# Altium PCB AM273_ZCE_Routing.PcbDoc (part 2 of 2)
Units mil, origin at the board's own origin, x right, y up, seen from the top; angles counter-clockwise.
Board outline 825 x 1150 mil, 4 copper layers (Top Layer, GND, Power, Bottom Layer), stack 60.63 mil thick; 37 components, 157 nets, 353 pads, 168 vias.
Unrouted connection lines stored in the file: 5.
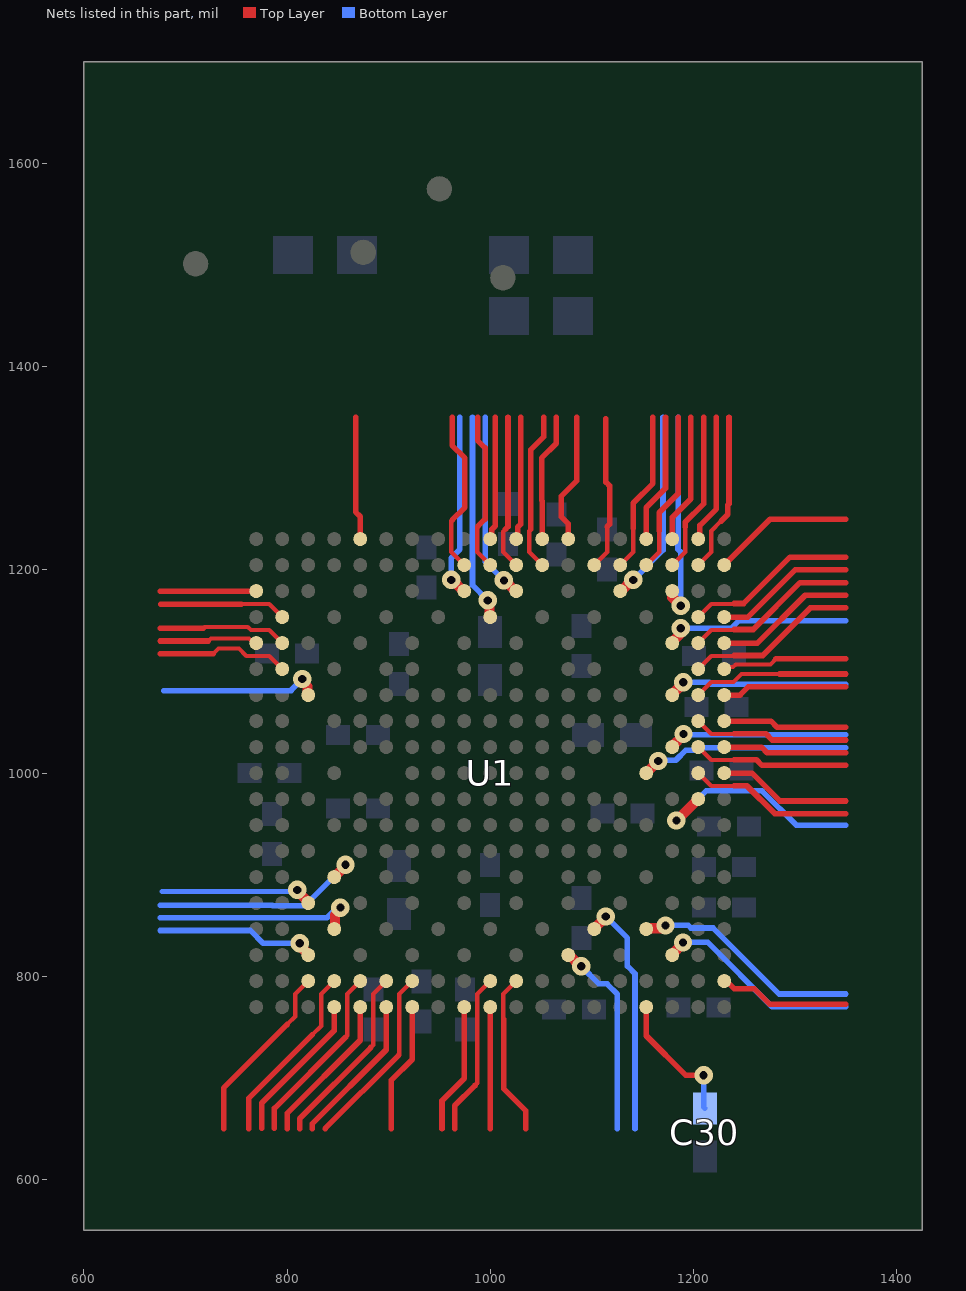
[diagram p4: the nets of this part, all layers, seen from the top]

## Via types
v1: diameter 18, hole 8, Top Layer to Bottom Layer, tented both sides, 168 vias

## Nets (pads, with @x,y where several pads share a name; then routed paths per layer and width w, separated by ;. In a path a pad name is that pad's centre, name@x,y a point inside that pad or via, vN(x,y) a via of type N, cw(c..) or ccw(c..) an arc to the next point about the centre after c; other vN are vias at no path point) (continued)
MSS_QSPI_CLK: U1.E1 | length 149.5
  Top Layer w5.5: 800,650 800,665 872.05,737.05 U1.E1@872.05,769.68
MSS_QSPI_CS: U1.F2 | length 180.5
  Top Layer w4: 882.5,730 884.84,732.34 884.84,782.48 U1.F2@897.64,795.28
  Top Layer w5.5: 812.5,650 812.5,660 882.5,730
MSS_QSPI_D0: U1.C2 | length 179.8
  Top Layer w4: 800,752.5 808.07,760.57 808.07,782.48 U1.C2@820.87,795.28
  Top Layer w5.5: 737.5,650 737.5,690 800,752.5
MSS_QSPI_D1: U1.D2 | length 180.1
  Top Layer w4: 825,742.5 833.66,751.16 833.66,782.48 U1.D2@846.46,795.28
  Top Layer w5.5: 762.5,650 762.5,680 825,742.5
MSS_QSPI_D2: U1.D1 | length 149
  Top Layer w5.5: 775,650.28 775,675 846.46,746.46 U1.D1@846.46,769.68
MSS_QSPI_D3: U1.E2 | length 180
  Top Layer w4: 857.5,740 859.25,741.75 859.25,782.48 U1.E2@872.05,795.28
  Top Layer w5.5: 787.5,650.28 787.5,670 857.5,740
MSS_RGMII_RCLK: U1.M19 | length 125.9
  Top Layer w5.5: U1.M19@1051.18,1230.32 1051.18,1267.69 1050.58,1268.3 1050.58,1310 1065,1324.42 1065,1350
MSS_RGMII_RCTL: U1.J17 | length 180.7
  Top Layer w10: v1(961.61,1190.14) 962.51,1190.14 973.51,1179.13 U1.J17@974.41,1179.13
  Bottom Layer w5.5: v1(961.61,1190.14) 961.61,1211.61 970,1220 970,1350
MSS_RGMII_RD0: U1.P18 | length 152
  Top Layer w4: U1.P18@1102.36,1204.72 1115.16,1217.52 1115.16,1242.34 1115,1242.5
  Top Layer w5.5: 1113.86,1348.86 1113.86,1286.36 1117.5,1282.73 1117.5,1245 1115,1242.5
MSS_RGMII_RD1: U1.N19 | length 128.7
  Top Layer w5.5: U1.N19@1076.77,1230.32 1076.71,1230.38 1076.71,1245.45 1070,1252.16 1070,1272.5 1085,1287.5 1085,1350
MSS_RGMII_RD2: U1.M18 | length 156.4
  Top Layer w4: 1040,1240 1038.39,1238.39 1038.39,1217.52 U1.M18@1051.18,1204.72
  Top Layer w5.5: 1040,1240 1040,1318.33 1052.5,1330.83 1052.5,1350
MSS_RGMII_RD3: U1.L19 | length 121.5
  Top Layer w5.5: U1.L19@1025.59,1230.32 1027.17,1231.9 1027.17,1242.17 1030,1245 1030,1350
MSS_RGMII_TCLK: U1.K19 | length 121.8
  Top Layer w5.5: U1.K19@1000,1230.32 1001.58,1231.9 1001.58,1240 1005,1243.42 1005,1350
MSS_RGMII_TCTL: U1.J18 | length 161.3
  Top Layer w4: 962.51,1248.98 961.61,1248.08 961.61,1217.52 U1.J18@974.41,1204.72
  Top Layer w5.5: 962.51,1248.98 975,1261.46 975,1310 962.5,1322.5 962.5,1350
MSS_RGMII_TD0: U1.L18 | length 152.5
  Top Layer w4: 1015,1240 1012.8,1237.8 1012.8,1217.52 U1.L18@1025.59,1204.72
  Top Layer w5.5: 1015,1240 1017.5,1242.5 1017.5,1350
MSS_RGMII_TD1: U1.L17 | length 184.5
  Top Layer w10: v1(1013.38,1189.64) 1014.23,1189.64 1024.74,1179.13 U1.L17@1025.59,1179.13
  Bottom Layer w5.5: 995,1350 995,1208.02 v1(1013.38,1189.64)
MSS_RGMII_TD2: U1.K16 | length 203.7
  Top Layer w10: v1(997.5,1170) 997.5,1167.84 999.28,1166.06 999.28,1154.27 U1.K16@1000,1153.54
  Bottom Layer w5.5: 982.5,1350 982.5,1185 v1(997.5,1170)
MSS_RGMII_TD3: U1.K18 | length 156.9
  Top Layer w4: 987.5,1242.5 987.21,1242.21 987.21,1217.52 U1.K18@1000,1204.72
  Top Layer w5.5: 987.5,1242.5 995,1250 995,1320 987.5,1327.5 987.5,1350
MSS_RS232_RX: U1.G2 | length 180.8
  Top Layer w4: 910,722.5 910.43,722.93 910.43,782.48 U1.G2@923.23,795.28
  Top Layer w5.5: 837.5,650 910,722.5
MSS_RS232_TX: U1.G1 | length 128.3
  Top Layer w5.5: 902.5,650 902.5,697.5 923.23,718.23 U1.G1@923.23,769.68
MSS_UARTA_RX: U1.U3 | length 203.2
  Top Layer w10: U1.U3@1179.13,820.87 1179.13,821.73 1189.8,832.4 v1(1189.8,833.26)
  Bottom Layer w5.5: v1(1189.8,833.26) 1214.24,833.26 1277.5,770 1350,770
MSS_UARTA_TX: U1.W2 | length 129.1
  Top Layer w5.5: U1.W2@1230.32,795.28 1232.56,795.28 1240.33,787.5 1260,787.5 1275,772.5 1350,772.5
MSS_UARTB_TX: U1.V9 | length 223.2
  Top Layer w10: v1(1183.19,953.19) 1183.35,953.19 1204.57,974.41 U1.V9@1204.72,974.41
  Bottom Layer w5.5: v1(1183.19,953.19) 1212.5,982.5 1267.5,982.5 1301.18,948.82 1350,948.82
OSC_CLK_OUT_AUDIO: U1.T4 | length 228.2
  Top Layer w10: U1.T4@1153.54,846.46 1154.27,847.18 1167.52,847.18 1170.34,850 v1(1172.5,850)
  Bottom Layer w5.5: v1@1167.5,852.5 v1@1169.17,854.17 ; v1(1172.5,850) 1195,850 1197.5,847.5 1219.4,847.5 1284.4,782.5 1350,782.5
PMIC_CLKOUT: U1.F1 | length 149.8
  Top Layer w5.5: 825,650 825,655 897.64,727.64 U1.F1@897.64,769.68
R\E\S\E\T\: U1.L2 | length 159.8
  Top Layer w4: 1013.09,757.5 1012.8,757.79 1012.8,782.48 U1.L2@1025.59,795.28
  Top Layer w5.5: 1013.09,757.5 1013.09,689.41 1035,667.5 1035,650
R\E\S\E\T\_\F\E\1\: U1.A15 | length 97.6
  Top Layer w4: 722.5,1130 725,1132.5 762.49,1132.5 767.04,1127.95 U1.A15@769.68,1127.95
  Top Layer w5.5: 675,1130 722.5,1130
R\E\S\E\T\_\F\E\2\: U1.B15 | length 127.4
  Top Layer w4: 717.43,1142.5 718.75,1143.82 761.32,1143.82 764.39,1140.75 765,1140.75 782.48,1140.75 U1.B15@795.28,1127.95
  Top Layer w5.5: 675,1142.5 717.43,1142.5
RCSS_GPIO_49: U1.E19 | length 121.6
  Top Layer w5.5: 867.5,1350 867.5,1257.05 872.05,1252.5 U1.E19@872.05,1230.32
RCSS_MIBSPIA_CLK: U1.T18 | length 158.3
  Top Layer w4: U1.T18@1153.54,1204.72 1166.34,1217.52 1166.34,1238.66
  Top Layer w5.5: 1166.34,1238.66 1166.34,1256.34 1185,1275 1185,1350
RCSS_MIBSPIA_CS0: U1.T19 | length 127.5
  Top Layer w5.5: U1.T19@1153.54,1230.32 1153.54,1261.31 1172.5,1280.27 1172.5,1350
RCSS_MIBSPIA_HOSTIRQ: U1.U18 | length 158.1
  Top Layer w4: U1.U18@1179.13,1204.72 1191.93,1217.52 1191.93,1242.36
  Top Layer w5.5: 1191.93,1242.36 1191.93,1246.93 1210,1265 1210,1350
RCSS_MIBSPIA_MISO: U1.R17 | length 189.3
  Top Layer w10: U1.R17@1127.95,1179.13 1128.85,1179.13 1139.85,1190.14 v1(1140.75,1190.14)
  Bottom Layer w5.5: v1(1140.75,1190.14) 1170,1219.39 1170,1350
RCSS_MIBSPIA_MOSI: U1.R18 | length 158.5
  Top Layer w4: U1.R18@1127.95,1204.72 1140.75,1217.52 1140.75,1240.75
  Top Layer w5.5: 1140.75,1240.75 1140.75,1265.75 1160,1285 1160,1350
RCSS_MIBSPIB_CLK: U1.V19 | length 127
  Top Layer w5.5: U1.V19@1204.72,1230.32 1206.31,1231.9 1206.31,1243.81 1222.5,1260 1222.5,1350
RCSS_MIBSPIB_CS0: U1.U17 | length 204.5
  Top Layer w10: U1.U17@1179.13,1179.13 1179.13,1173.01 v1(1187.5,1164.64)
  Bottom Layer w5.5: 1185,1350 1185,1225 1184.78,1224.78 1184.78,1220.22 1187.5,1217.5 v1(1187.5,1164.64)
RCSS_MIBSPIB_HOSTIRQ: U1.W18 | length 138.4
  Top Layer w5.5: U1.W18@1230.32,1204.72 1275.59,1250 1350,1250
RCSS_MIBSPIB_MISO: U1.V18 | length 157.8
  Top Layer w4: U1.V18@1204.72,1204.72 1217.52,1217.52 1217.52,1238.27 1227.33,1248.08
  Top Layer w5.5: 1227.33,1248.08 1233.78,1254.53 1233.78,1263.78 1235,1265 1235,1350
RCSS_MIBSPIB_MOSI: U1.U19 | length 127.3
  Top Layer w5.5: U1.U19@1179.13,1230.32 1179.13,1251.63 1197.5,1270 1197.5,1350
RCSS_UARTA_RX: U1.B16 | length 124.8
  Top Layer w4: 755,1166.34 782.48,1166.34 U1.B16@795.28,1153.54
  Top Layer w5.5: 675.75,1166.34 755,1166.34
RCSS_UARTA_TX: U1.A17 | length 94.7
  Top Layer w5.5: 675,1179.13 U1.A17@769.68,1179.13
TCK: U1.C3 | length 157.8
  Top Layer w10: v1(812.5,832.5) 812.5,830.34 815.56,827.27 815.56,827.19 820.87,821.89 U1.C3@820.87,820.87
  Bottom Layer w5.5: 675,845 763.9,845 776.4,832.5 v1(812.5,832.5)
TDI: U1.C5 | length 151
  Top Layer w10: v1(810,885) 810,883.94 820.87,873.07 U1.C5@820.87,872.05
  Bottom Layer w5: 677.04,883.55 808.55,883.55 v1(810,885)
TDO: U1.D6 | length 226.7
  Top Layer w10: U1.D6@846.46,897.64 857.5,908.68 v1(857.5,909.68)
  Bottom Layer w5.5: 675,870 785.36,870 786.11,869.25 817.07,869.25 v1(857.5,909.68) 857.18,909.68 850,902.5
TEMP_1_SENSOR: U1.P4 | length 237.8
  Top Layer w10: U1.P4@1102.36,846.46 1102.36,846.95 1113.74,858.33 v1(1113.74,858.83)
  Bottom Layer w5.5: v1(1113.74,858.83) 1135,837.58 1135,810 1142.5,802.5 1142.5,650
TEMP_2_SENSOR: U1.N3 | length 196.6
  Top Layer w10: U1.N3@1076.77,820.87 1077.67,820.87 1088.67,809.86 v1(1089.57,809.86)
  Bottom Layer w5.5: v1(1089.57,809.86) 1106.93,792.5 1115,792.5 1125,782.5 1125,650
TMS: U1.D4 | length 205.2
  Top Layer w10: U1.D4@846.46,846.46 847.18,847.18 847.18,860.01 852.5,865.34 v1(852.5,867.5)
  Bottom Layer w5.5: 675,857.5 839.12,857.5 849.12,867.5 v1(852.5,867.5)
TRACE_CLK: U1.W12 | length 122.2
  Top Layer w5.5: U1.W12@1230.32,1051.18 1276.32,1051.18 1282.5,1045 1350,1045
TRACE_CTL: U1.V12 | length 153.3
  Top Layer w4: U1.V12@1204.72,1051.18 1217.52,1038.39 1239.71,1038.39 1240,1038.68
  Top Layer w5.5: 1240,1038.68 1271.32,1038.68 1277.5,1032.5 1350,1032.5
TRACE_D0: U1.V16 | length 169.4
  Top Layer w4: U1.V16@1204.72,1153.54 1217.52,1166.34 1239.43,1166.34 1240,1166.91
  Top Layer w5.5: 1240,1166.91 1249.41,1166.91 1295,1212.5 1349.72,1212.5
TRACE_D1: U1.U15 | length 183.6
  Top Layer w10: U1.U15@1179.13,1127.95 1179.13,1128.98 1185.97,1135.81 1185.97,1140.97 v1(1187.5,1142.5)
  Bottom Layer w5.5: v1(1187.5,1142.5) 1237.5,1142.5 1245,1150 1350,1150
TRACE_D2: U1.W16 | length 138.9
  Top Layer w5.5: U1.W16@1230.32,1153.54 1253.54,1153.54 1300,1200 1350,1200
TRACE_D3: U1.V15 | length 169.9
  Top Layer w4: U1.V15@1204.72,1127.95 1217.52,1140.75 1239.43,1140.75 1240,1141.32
  Top Layer w5.5: 1240,1141.32 1258.82,1141.32 1305,1187.5 1350,1187.5
TRACE_D4: U1.W15 | length 139.2
  Top Layer w5.5: U1.W15@1230.32,1127.95 1262.95,1127.95 1310,1175 1350,1175
TRACE_D5: U1.V14 | length 170.2
  Top Layer w4: U1.V14@1204.72,1102.36 1217.52,1115.16 1239.43,1115.16 1240,1115.73
  Top Layer w5.5: 1240,1115.73 1268.23,1115.73 1315,1162.5 1350,1162.5
TRACE_D6: U1.U13 | length 177.8
  Top Layer w10: U1.U13@1179.13,1076.77 1179.13,1077.65 1189.92,1088.43 v1(1189.92,1089.31)
  Bottom Layer w5.5: v1(1189.92,1089.31) 1215.69,1089.31 1217.5,1087.5 1350,1087.5
TRACE_D7: U1.W14 | length 123.9
  Top Layer w4: U1.W14@1230.32,1102.36 1232.19,1104.23 1238.91,1104.23 1241.65,1106.98 1275.73,1106.98 1281.25,1112.5
  Top Layer w5.5: 1281.25,1112.5 1350,1112.5
TRACE_D8: U1.V13 | length 153.9
  Top Layer w4: U1.V13@1204.72,1076.77 1217.52,1089.57 1239.57,1089.57 1247.5,1097.5 1285,1097.5
  Top Layer w5.5: 1285,1097.5 1350,1097.5
TRACE_D9: U1.W13 | length 123.1
  Top Layer w5.5: U1.W13@1230.32,1076.77 1245.83,1076.77 1254.06,1085 1350,1085
TRACE_D10: U1.U11 | length 177.6
  Top Layer w10: U1.U11@1179.13,1025.59 1179.13,1026.49 1190.14,1037.49 v1(1190.14,1038.39)
  Bottom Layer w5.5: v1(1190.14,1038.39) 1191.02,1037.5 1350,1037.5
TRACE_D11: U1.V11 | length 153
  Top Layer w4: U1.V11@1204.72,1025.59 1217.52,1012.8 1239.71,1012.8 1240,1013.09
  Top Layer w5.5: 1240,1013.09 1261.91,1013.09 1267.5,1007.5 1350,1007.5
TRACE_D12: U1.W11 | length 122
  Top Layer w5.5: U1.W11@1230.32,1025.59 1266.91,1025.59 1272.5,1020 1350,1020
TRACE_D13: U1.V10 | length 162.1
  Top Layer w4: U1.V10@1204.72,1000 1217.52,987.21 1239.71,987.21 1240,987.5
  Top Layer w5.5: 1240,987.5 1252.5,987.5 1280,960 1350,960
TRACE_D14: U1.W10 | length 131.1
  Top Layer w5.5: U1.W10@1230.32,1000 1257.5,1000 1285,972.5 1350,972.5
TRACE_D15: U1.T10 | length 206.9
  Top Layer w10: U1.T10@1153.54,1000 1153.54,1000.09 1165.32,1011.87 v1(1165.32,1011.96)
  Bottom Layer w5.5: v1(1165.32,1011.96) 1165.94,1012.57 1182.57,1012.57 1192.5,1022.5 1202.5,1022.5 1205,1025 1350,1025
VBGAP: C30.1 U1.T1 | length 133.9
  Top Layer w5.5: U1.T1@1153.54,769.68 1153.54,741.46 1192.5,702.5 v1(1210,702.5)
  Bottom Layer w5.5: v1(1210,702.5) 1210,671.28 C30.1@1211.28,670
W\A\R\M\R\E\S\E\T\_\I\N\_\F\E\1\: U1.B14 | length 130.7
  Top Layer w4: 727.5,1117.5 732.5,1122.5 752.5,1122.5 759.84,1115.16 782.48,1115.16 U1.B14@795.28,1102.36
  Top Layer w5.5: 675,1117.5 727.5,1117.5
W\A\R\M\R\E\S\E\T\_\I\N\_\F\E\2\: U1.C13 | length 159.8
  Top Layer w10: v1(815,1092.5) 815,1090.34 820.14,1085.19 820.14,1077.49 U1.C13@820.87,1076.77
  Bottom Layer w5.5: 678.48,1080.98 804.02,1080.98 804.02,1081.52 v1(815,1092.5)
WARM_RESET: U1.K1 | length 119.7
  Top Layer w5.5: 1000,650 U1.K1@1000,769.68
XREF_CLK0: U1.J1 | length 128.8
  Top Layer w5.5: 952.5,650 952.5,677.5 974.41,699.41 U1.J1@974.41,769.68
XREF_CLK1: U1.K2 | length 159.8
  Top Layer w4: 985,692.5 987.21,694.71 987.21,782.48 U1.K2@1000,795.28
  Top Layer w5.5: 965,650 965,672.5 985,692.5

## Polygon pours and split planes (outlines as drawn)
1V8_AM273 on Top Layer "TOP_LAYER_1V8_AM273_P039" (solid, remove dead copper, pour order 39): 1170,932.5 1195,932.5 1195,875 1185,865 1170,865 1157.5,877.5 1157.5,920
1V2_VDD on Top Layer "TOP_LAYER_1V2_VDD_P002" (solid, remove dead copper, pour order 2): 922.5,900 922.5,865 970,817.5 992.5,817.5 992.5,852.5 1072.5,852.5 1085,865 1085,895 1080,900
GND on Top Layer "TOP_LAYER_GND_P036" (solid, remove dead copper, pour order 36): 755,1462.5 755,1530 825,1600 1092.5,1600 1152.5,1540 1152.5,1437.5 1112.5,1437.5 1000,1550 837.5,1550 825,1537.5 825,1462.5
1V8_AM273 on Top Layer "TOP_LAYER_1V8_AM273_P035" (solid, remove dead copper, pour order 35): 675,1540 675,1505 697.5,1482.5 722.5,1482.5 745,1505 745,1540
3V3_AM273 on Top Layer "TOP_LAYER_3V3_AM273_P033" (solid, remove dead copper, pour order 33): 925,1462.5 925,1540 850,1540 850,1462.5
1V2_VDD on Top Layer "TOP_LAYER_1V2_VDD_P032" (solid, remove dead copper, pour order 32): 942.5,1537.5 942.5,1437.5 992.5,1437.5 1030,1475 1030,1500 992.5,1537.5
GND on Top Layer "TOP_LAYER_GND_P024" (solid, remove dead copper, pour order 24): 675,1350 1350,1350 1350,650 675,650
1V2_VDD on Top Layer "TOP_LAYER_1V2_VDD_P012" (solid, remove dead copper, pour order 12): 1072.5,1212.5 1055,1195 993.61,1130 1092.5,1130 1092.5,1180 1097.5,1185 1097.5,1197.5 1082.5,1212.5
1V8_AM273 on Top Layer "TOP_LAYER_1V8_AM273_P010" (solid, remove dead copper, pour order 10): 805,940 817.5,940 830,952.5 830,1037.5 817.5,1050 805,1050
GND on Top Layer "TOP_LAYER_GND_P004" (solid, remove dead copper, pour order 4): 897.5,1117.5 820,1040 820,917.5 865,917.5 865,870 890,870 937.5,917.5 1072.5,917.5 1100,890 1160,890 1170,900 1170,1155 1157.5,1167.5 1117.5,1167.5 1067.5,1117.5
1V2_VDD on Top Layer "TOP_LAYER_1V2_VDD_P003" (solid, remove dead copper, pour order 3): 1100,1027.5 1135,1027.5 1145,1017.5 1145,982.5 1135,972.5 1100,972.5
1V2_VDD on Top Layer "TOP_LAYER_1V2_VDD_P001" (solid, remove dead copper, pour order 1): 900,1027.5 900,972.5 867.5,972.5 855,985 855,1017.5 865,1027.5
1V2_VDD on Top Layer "TOP_LAYER_1V2_VDD_P000" (solid, remove dead copper, pour order 0): 915,1135 925,1145 1090,1145 1090,1115 1075,1100 925,1100 915,1110
1V2_VDD on Bottom Layer "BOTTOM_LAYER_1V2_VDD_P011" (solid, remove dead copper, pour order 11): 1007.5,1237.5 1072.5,1237.5 1100,1210 1100,1185 1095,1180 1040,1180 1007.5,1212.5
GND on Bottom Layer "BOTTOM_LAYER_GND_P040" (solid, remove dead copper, pour order 40): 827.5,1540 750,1540 750,1450 827.5,1450
GND on Bottom Layer "BOTTOM_LAYER_GND_P029" (solid, remove dead copper, pour order 29): 1060,1540 1150,1540 1150,1430 1060,1430
GND on Bottom Layer "BOTTOM_LAYER_GND_P028" (solid, remove dead copper, pour order 28): 675,1350 1350,1350 1350,650 675,650
3V3_AM273 on Bottom Layer "BOTTOM_LAYER_3V3_AM273_P025" (solid, remove dead copper, pour order 25): 847.5,1540 937.5,1540 937.5,1450 847.5,1450
1V2_VDD on Bottom Layer "BOTTOM_LAYER_1V2_VDD_P023" (solid, remove dead copper, pour order 23): 1040,1540 1040,1422.5 940,1422.5 940,1540
1V8_AM273 on Bottom Layer "BOTTOM_LAYER_1V8_AM273_P013" (solid, remove dead copper, pour order 13): 825,1055 785,1055 755,1025 755,957.5 780,932.5 825,932.5
1V2_VDD on Bottom Layer "BOTTOM_LAYER_1V2_VDD_P009" (solid, remove dead copper, pour order 9): 1070,842.5 1070,892.5 1060,902.5 932.5,902.5 910,880 910,842.5
1V2_VDD on Bottom Layer "BOTTOM_LAYER_1V2_VDD_P008" (solid, remove dead copper, pour order 8): 1070,1105 1067.5,1102.5 900,1102.5 900,1145 1070,1145
1V2_VDD on Bottom Layer "BOTTOM_LAYER_1V2_VDD_P007" (solid, remove dead copper, pour order 7): 1162.5,950 1162.5,1050 1105,1050 1105,950
1V2_VDD on Bottom Layer "BOTTOM_LAYER_1V2_VDD_P006" (solid, remove dead copper, pour order 6): 837.5,1047.5 837.5,955 897.5,955 897.5,1047.5
GND on Bottom Layer "BOTTOM_LAYER_GND_P005" (solid, remove dead copper, pour order 5): 877.5,1080 877.5,1027.5 912.5,1027.5 912.5,975 877.5,975 877.5,900 912.5,900 930,917.5 1062.5,917.5 1080,900 1120,900 1120,970 1085,970 1085,1027.5 1147.5,1090 1147.5,1117.5 1137.5,1127.5 1092.5,1127.5 1082.5,1117.5 1082.5,1087.5 1075,1080
1V8_AM273 on Power "POWER_1V8_AM273_P037" (solid, remove dead copper, pour order 37): 675,1540 750,1540 750,1195 817.5,1127.5 752.5,1062.5 750,1062.5 675,1137.5
GND on Power "POWER_GND_P041" (solid, remove dead copper, pour order 41): 675.18,1540 1350.18,1540 1350.18,649.69 675.18,649.69
3V3_AM273 on Power "POWER_3V3_AM273_P026" (solid, remove dead copper, pour order 26): 1180,1082.5 1115,1147.5 1107.5,1147.5 1095,1135 1095,1100 1147.5,1047.5
3V3_AM273 on Power "POWER_3V3_AM273_P022" (solid, remove dead copper, pour order 22): 835,1097.5 882.5,1145 907.5,1145 907.5,1105 867.5,1065
3V3_AM273 on Power "POWER_3V3_AM273_P020" (solid, remove dead copper, pour order 20): 850,1540 850,1167.5 892.5,1125 932.5,1125 932.5,1540
3V3_AM273 on Power "POWER_3V3_AM273_P019" (solid, remove dead copper, pour order 19): 857.5,1097.5 835,1097.5 822.5,1085 822.5,1045 802.5,1025 802.5,957.5 825,935 810,920 810,879.34 861.84,827.5 902.5,827.5 902.5,1052.5
3V3_AM273 on Power "POWER_3V3_AM273_P017" (solid, remove dead copper, pour order 17): 1157.5,1075.07 1157.5,935 1135,912.5 1135,882.5 1137.5,880 1160,880 1220,940 1220,1061.57 1194.07,1087.5 1169.93,1087.5
1V2_VDD on Power "POWER_1V2_VDD_P016" (solid, remove dead copper, pour order 16): 930,1100 930,1540 1030,1540 1030,1395 1030,1257.5 1090,1197.5 1090,1100
1V8_AM273 on Power "POWER_1V8_AM273_P038" (solid, remove dead copper, pour order 38): 742.5,842.5 820,765 1167.5,765 1287.5,885 1287.5,1122.5 1172.5,1237.5 1125,1237.5 1060,1172.5 1060,1150 815,1150 742.5,1077.5
GND on Power "POWER_GND_P014" (solid, remove dead copper, pour order 14): 935,1075 1042.5,1075 1075,1042.5 1075,982.5 1075,967.5 1032.5,925 932.5,925 925,932.5 925,940 925,980 925,1020 912.5,1032.5 912.5,1047.5 925,1060 925,1065
1V2_VDD on Power "POWER_1V2_VDD_P015" (solid, remove dead copper, pour order 15): 867.5,942.5 867.5,955 860,962.5 860,1065 900,1105 900,1115 935,1150 1055,1150 1155,1050 1155,937.5 1142.5,925 1130,925 1045,840 952.3,840 890,903.02 890,920
3V3_AM273 on GND "GND_3V3_AM273_P030" (solid, remove dead copper, pour order 30): 1125,1122.5 1085,1082.5 922.5,1082.5 880,1125 880,1205 895,1220 1100,1220 1125,1195
3V3_AM273 on GND "GND_3V3_AM273_P027" (solid, remove dead copper, pour order 27): 875,895 902.5,922.5 1077.5,922.5 1110,890 1137.5,890 1147.5,880 1147.5,782.5 1140,775 892.5,775 875,792.5
GND on GND "GND_GND_P031" (solid, remove dead copper, pour order 31): 675.18,1540 1350.18,1540 1350.18,649.88 675.18,649.88

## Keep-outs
Keep-Out Layer:
  text ".Layer_Name" at 577,-858.49 h60

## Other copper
Top Layer:
  text ".Layer_Name" at 577,-858.49 h60
Bottom Layer:
  text ".Layer_Name" at 577,-858.49 h60

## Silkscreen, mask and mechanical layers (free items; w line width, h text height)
Top Overlay:
  text ".Layer_Name" at 577,-858.49 h60
Bottom Overlay:
  text ".Layer_Name" at 577,-858.49 h60
Top Paste:
  text ".Layer_Name" at 577,-858.49 h60
Bottom Paste:
  text ".Layer_Name" at 577,-858.49 h60
Top Solder:
  text ".Layer_Name" at 577,-858.49 h60
  text ".Layer_Name" at 577,-858.49 h60
Bottom Solder:
  text ".Layer_Name" at 577,-858.49 h60
Drill Guide:
  text ".Layer_Name" at 577,-858.49 h60
M1 Board Outline:
  lines w10: 0,0 0,3450 4950,3450 4950,0 0,0 ; 600,550 600,1700 1425,1700 1425,550 600,550
  text ".Layer_Name" at 577,-858.49 h60
M2 Board Dimensions:
  rectangle: 0,-275 125,-150
  rectangle: 125,-400 500,-275
  lines w7: 0,-275 1000,-275 ; 125,-400 125,-150 ; 250,-400 250,-150 ; 500,-400 500,-150 ; 750,-400 750,-150 ; 0,-400 1000,-400 1000,-150 0,-150 0,-400
  text ".Layer_Name" at 577,-858.49 h60
M3 3D STEP Top:
  text ".Layer_Name" at 577,-858.49 h60
M4 3D STEP Bottom:
  text ".Layer_Name" at 577,-858.49 h60
M5 Assembly Top:
  lines w10: -292,-930.17 6308,-930.17 ; -292,-726.83 6310,-726.83 ; -292,-523.5 -292,-1133.5 3713,-1133.5 6310,-1133.5 6310,-523.5 -291.5,-523.5 -291.5,-1133.5 1284,-1133.5 ; 2173,-1133.5 2173,-523.5 ; 3440,-726.83 3440,-523.5 ; 4280,-726.83 4280,-523.5 ; 4902,-1140 4902,-937.17
  text "COMPONENTS MARKED 'DNP' SHOULD NOT BE POPULATED." at 1153.5,-318.5 h60
  text "ASSEMBLY VARIANT:" at 1153,-434 h60
  text ".VariantName" at 2189,-434 h60
  text "PCB VIEWED FROM TOP SIDE" at -228.5,-655.67 h60
  text "BOARD #:" at 2248,-655.67 h60
  text ".PRJ_Number" at 2793.5,-655.67 h60
  text "REV:" at 3638,-655.67 h60
  text ".PCB_Rev" at 3929.5,-655.67 h60
  text "SVN REV:" at 4476,-655.67 h60
  text ".VersionControl_RevNumber" at 4982,-655.67 h60
  text "TID #:" at 2248,-859 h60
  text ".TID" at 2793.5,-859 h60
  text "PLOT NAME =" at -228.5,-1064.34 h60
  text ".plot_File_Name" at 577,-1064.34 h60
  text "GENERATED    :" at 2250,-1064.34 h60
  text ".Print_Date" at 3119.5,-1064.34 h60
  text ".Print_Time" at 3848.5,-1064.34 h60
  text "TEXAS INSTRUMENTS" at 5113,-1064.34 h60
M6 Assembly Bottom:
  lines w10: -292.5,-727.33 6309.5,-727.33 ; -290.5,-930.67 6309.5,-930.67 ; 1115.5,-1140.5 1115.5,-937.67 ; 1737.5,-727.33 1737.5,-524 ; 2577.5,-727.33 2577.5,-524 ; 3844.5,-1134 3844.5,-524 ; 4733.5,-1134 6309,-1134 6309,-524 -292.5,-524 -292.5,-1134 2304.5,-1134 6309.5,-1134 6309.5,-524
  text "COMPONENTS MARKED 'DNP' SHOULD NOT BE POPULATED." at 6102,-318 h60
  text ".VariantName" at 5058,-434 h60
  text "ASSEMBLY VARIANT:" at 6097,-434 h60
  text ".VersionControl_RevNumber" at 1035.5,-656.17 h60
  text "SVN REV:" at 1541.5,-656.17 h60
  text ".PCB_Rev" at 2088,-656.17 h60
  text "REV:" at 2379.5,-656.17 h60
  text ".PRJ_Number" at 3224,-656.17 h60
  text "BOARD #:" at 3769.5,-656.17 h60
  text "PCB VIEWED FROM BOTTOM SIDE" at 6246,-656.17 h60
  text ".TID" at 3224,-859.5 h60
  text "TID #:" at 3769.5,-859.5 h60
  text "TEXAS INSTRUMENTS" at 904.5,-1064.84 h60
  text ".Print_Time" at 2169,-1064.84 h60
  text ".Print_Date" at 2898,-1064.84 h60
  text "GENERATED    :" at 3767.5,-1064.84 h60
  text ".plot_File_Name" at 5440.5,-1064.84 h60
  text "PLOT NAME =" at 6246,-1064.84 h60
M9 Title Sheet:
  drawing of 57 lines, arcs and shapes, not listed
  text "1" at 739.84,8036.5 h70
  text "2" at 3235.5,8036.5 h70
  text "3" at 5724.84,8036.5 h70
  text "4" at 8231.51,8036.5 h70
  text "5" at 10730.5,8036.5 h70
  text "6" at 13235.5,8036.5 h70
  text "A" at -416.5,6893.5 h70
  text "A" at 14383.5,6893.5 h70
  text "B" at -416.5,4513.5 h70
  text "B" at 14383.5,4513.5 h70
  text "C" at -416.5,2138.5 h70
  text "C" at 14383.5,2138.5 h70
  text "PROJECT TITLE:" at 11343.5,277.5 h45
  text ".PRJ_Title" at 11393.5,144.17 h70
  text "DESIGNED FOR:" at 11343.5,-23.5 h45
  text ".PRJ_Customer" at 11393.5,-163.5 h70
  text "D" at -416.5,-231.5 h70
  text "D" at 14383.5,-231.5 h70
  text "FILE NAME:" at 11343.5,-323.5 h45
  text ".PCB_File_Name_No_Path" at 11393.5,-443.5 h70
  text "Texas Instruments (TI) and/or its licensors do not warrant the accuracy or completeness of this specification" at 6374,-605.34 h45
  text "ENGINEER:" at 11343.5,-613.5 h45
  text "LAYOUT BY:" at 12848.5,-613.5 h45
  text "or any information contained therein. TI and/or its licensors do not warrant that this design will meet" at 6329.01,-718 h45
  text ".PRJ_Engineer" at 11393.5,-768.49 h70
  text ".PCB_Layout" at 12899,-768.49 h70
  text "the specifications, will be suitable for your application or fit for any particular purpose, or will operate in" at 6329.01,-830.67 h45
  text ".Layer_Name" at 577,-858.49 h60
  text "ALTIUM DESIGNER VERSION:" at 12848.5,-923.5 h45
  text "an implementation. TI and/or its licensors do not warrant that the design is production worthy. You should" at 6329.01,-943.33 h45
  text "completely validate and test your design implementation to confirm the system functionality for your application." at 6374,-1056 h45
  text ".print_Scale" at 11393.5,-1056.83 h70
  text ".Application_BuildNumber" at 12899,-1056.83 h70
  text "1" at 739.84,-1263.5 h70
  text "2" at 3235.5,-1263.5 h70
  text "3" at 5724.84,-1263.5 h70
  text "4" at 8231.51,-1263.5 h70
  text "5" at 10730.5,-1263.5 h70
  text "6" at 13235.5,-1263.5 h70
M10 Fab Notes:
  drawing of 189 lines, arcs and shapes, not listed
  text "DESIGN INFORMATION" at 12382.02,6356.17 h60
  text "MIN. TRACK WIDTH:" at 11737.46,6224.05 h60
  text "4" at 12833.7,6224.05 h60
  text "MIL" at 12988.46,6224.05 h60
  text "3.515" at 12667.32,6102.36 h60
  text "MIN. CLEARANCE:" at 11737.46,6099.92 h60
  text "MIL" at 12988.46,6099.92 h60
  text "MIN. VIA PAD SIZE:" at 11737.46,5975.8 h60
  text "18" at 12803.71,5975.8 h60
  text "MIL" at 12988.46,5975.8 h60
  text "0.05mm (2MIL)" at 12432.46,5845.9 h60
  text "MINIMUM ANNULAR RING" at 11408.23,5837.67 h60
  text "EXTERNAL" at 13140.46,5837.67 h60
  text "PER" at 11608.23,5727.55 h60
  text "IPC-D-275 CLASS 2 LEVEL C" at 11828.23,5727.54 h60
  text "MIL, HOLES" at 13316.46,5627.07 h60
  text "+/-" at 12924,5618.48 h60
  text "+/-" at 13778,5618.48 h60
  text "REGISTRATION TOLERANCES:" at 11408.23,5617.42 h60
  text "METAL" at 12608,5617.42 h60
  text "5" at 13184.2,5617.42 h60
  text "3" at 14017.2,5617.42 h60
  text "MIL" at 14133.46,5617.42 h60
  text "HOLE SIZE TOLERANCE (UNLESS OTHERWISE SPECIFIED):" at 11408.23,5519.1 h60
  text "+/-" at 13778,5516.23 h60
  text "3" at 14017.2,5515.17 h60
  text "MIL" at 14133.46,5515.17 h60
  text "MATERIAL:" at 11333.46,5377.52 h60
  text "FR-4 High Tg" at 12319.9,5249 h60
  text "X" at 12175.46,5241.01 h60
  text "FR-408" at 11754.46,5236.49 h60
  text "OTHER" at 13242.46,5236.49 h60
  text "62 MIL (1.6mm) +/-10%" at 12074.56,5093.46 h60
  text "X" at 11954.46,5091.01 h60
  text "THICKNESS:" at 11408.23,5085.24 h60
  text "OTHER" at 13359.46,5085.24 h60
  text "TOLERANCE:" at 11408.23,4946.92 h60
  text "X" at 12256.46,4946.92 h60
  text "ANSI IPC-6012 TYPE 3 CLASS 2" at 12434.48,4946.92 h60
  text "OTHER +/-" at 12434.46,4802.73 h60
  text "BOW & TWIST:" at 11408.23,4657.54 h60
  text "X" at 12256.46,4657.54 h60
  text "ANSI IPC-6012 TYPE 3 CLASS 2" at 12434.48,4657.54 h60
  text "OTHER +/-" at 12434.46,4510.85 h60
  text "DRILLING:" at 11333.46,4380.23 h60
  text "NC_DRILL FILES" at 13094.46,4275.04 h60
  text "REFERENCE:" at 11408.23,4271.1 h60
  text "X" at 12065.46,4271.01 h60
  text "AS SHOWN" at 12243.46,4271.1 h60
  text "X" at 12966.46,4271.1 h60
  text "OTHER" at 13392.46,4128.85 h60
  text "PTH COPPER THICKNESS:" at 11407.91,4125.32 h60
  text "X" at 12547.14,4125.32 h60
  text "20-30 um" at 12675.14,4125.32 h60
  text "BOARD FINISH:" at 11333.46,3977.73 h60
  text "SILKSCREEN:" at 11488.68,3867.6 h60
  text "X" at 12446.46,3867.6 h60
  text "TOP" at 12563.46,3867.6 h60
  text "X" at 12956.46,3867.6 h60
  text "BOTTOM" at 13074.46,3867.6 h60
  text "SILKSCREEN COLOR:" at 11488.68,3712.41 h60
  text "X" at 12445.46,3712.41 h60
  text "WHITE" at 12563.46,3712.41 h60
  text "OTHER" at 13074.46,3712.41 h60
  text "X" at 12576.46,3568.96 h60
  text "GREEN" at 12694.46,3568.96 h60
  text "OTHER" at 13312.46,3568.96 h60
  text "SOLDER RESIST COLOR:" at 11488.68,3562.1 h60
  text "X" at 12576.46,3414.71 h60
  text "MATTE" at 12694.46,3414.71 h60
  text "SEMI-GLOSS" at 13312,3414.07 h60
  text "IMMERSION GOLD (ENIG)" at 12394.46,3241.94 h60
  text "ENEPIG" at 13732,3234.72 h60
  text "SURFACE FINISH:" at 11333.46,3233.72 h60
  text "X" at 12216.46,3233.72 h60
  text "IMM. TIN/SILVER OR EQUIV" at 11663,3096.4 h60
  text "OTHER" at 13094.46,3092.47 h60
  text "ARRAY/PANEL:" at 11333.46,2937.09 h60
  text "CUT AND TRIM PER M1 BOARD OUTLINE" at 12394.46,2928.87 h60
  text "N.C. ROUTE" at 12394.46,2792.9 h60
  text "X" at 13082.46,2792.9 h60
  text "V. SCORE" at 13260.46,2792.9 h60
  text "CERTIFICATION:" at 11333.46,2663.77 h60
  text "MATERIALS AND WORKMANSHIP FOR ALL PCBS" at 12058.46,2663.77 h60
  text "TO MEET OR EXCEED THE REQUIREMENTS OF:" at 12058.46,2569.71 h60
  text "X" at 11695.97,2441.08 h60
  text "ANSI IPC-A-600F CLASS ->" at 11823.96,2441.08 h60
  text "X" at 13471.97,2441.08 h60
  text "2" at 13581.96,2441.08 h60
  text "1" at 13266.96,2439.58 h60
  text "3" at 13935.96,2439.58 h60
  text "X" at 12507.97,2293.39 h60
  text "RoHS" at 12635.96,2293.39 h60
  text "OTHER" at 13280.36,2293.39 h60
  text "PER ORDER" at 13677.42,2293.39 h60
  text "ALL BOARDS MUST MEET OR EXCEED UL94-V0 REQUIREMENTS." at 11361,2139.57 h60
  text "PCB MUST BEAR THE UL94V-0 UL REGISTERED MATERIAL ID NUMBER" at 11361,2023.5 h60
  text "ADDITIONAL REQUIREMENTS:" at 11333.46,1854.08 h60
  text "MICROSECTION:" at 11408.23,1746.95 h60
  text "YES" at 12313.96,1746.95 h60
  text "REQUIRED" at 13175.46,1602.62 h60
  text "BARE BOARD ELEC. TEST:" at 11408.23,1599.76 h60
  text "NONE" at 12713.96,1599.76 h60
  text "X" at 13057.46,1599.76 h60
  text "PER ORDER" at 13767.46,1599.76 h60
  text "XX MIL VIAS REQUIRE NON-CONDUCTIVE FILL AND PLANARIZE" at 11576.38,1394.82 h59
  text "XX MIL VIAS REQUIRE CONDUCTIVE FILL AND PLANARIZE" at 11584.38,1290.84 h60
  text "OUTER XX MIL TRACES REQUIRE 50 OHM SINGLE-ENDED IMPEDANCE" at 11583.39,1127.46 h58
  text "LAYER 2 & 3 (INNER LAYERS) XX MIL WIDE, XX MIL SPACE / TRACES REQUIRE 100 OHM DIFFERENTIAL IMPEDANCE" at 11575.39,891.74 h60
  text ".Layer_Name" at 577,-858.49 h60
M11 Gerber Information:
  lines w10: -292,-930.17 6308,-930.17 ; -292,-726.83 6310,-726.83 ; -292,-523.5 -292,-1133.5 3713,-1133.5 6310,-1133.5 6310,-523.5 -291.5,-523.5 -291.5,-1133.5 1284,-1133.5 ; 2173,-1133.5 2173,-523.5 ; 3440,-726.83 3440,-523.5 ; 4280,-726.83 4280,-523.5 ; 4902,-1140 4902,-937.17
  text "ALL ARTWORK VIEWED FROM TOP SIDE" at -228.5,-655.67 h60
  text "BOARD #:" at 2248,-655.67 h60
  text ".PRJ_Number" at 2793.5,-655.67 h60
  text "REV:" at 3638,-655.67 h60
  text ".PCB_Rev" at 3929.5,-655.67 h60
  text "SVN REV:" at 4476,-655.67 h60
  text ".VersionControl_RevNumber" at 4982,-655.67 h60
  text "LAYER NAME =" at -228.5,-858.49 h60
  text "TID #:" at 2248,-859 h60
  text ".TID" at 2793.5,-859 h60
  text "PLOT NAME =" at -228.5,-1064.34 h60
  text ".plot_File_Name" at 577,-1064.34 h60
  text "GENERATED    :" at 2250,-1064.34 h60
  text ".Print_Date" at 3119.5,-1064.34 h60
  text ".Print_Time" at 3848.5,-1064.34 h60
  text "TEXAS INSTRUMENTS" at 5113,-1064.34 h60
M12 Stackup:
  drawing of 295 lines, arcs and shapes, not listed
  text "Layer" at 9821.59,7874.94 h60
  text "Name" at 10231.51,7874.94 h60
  text "Material" at 11161.25,7874.94 h60
  text "Thickness" at 12021.02,7874.94 h60
  text "Constant" at 12670.85,7874.94 h60
  text "Board Layer Stack" at 13240.71,7874.94 h60
  text "Top Overlay" at 10231.51,7754.94 h60
  text "Top Solder" at 10231.51,7634.94 h60
  text "Solder Resist" at 11161.25,7634.94 h60
  text "0.39mil" at 12021.02,7634.94 h60
  text "3.3" at 12670.85,7634.94 h60
  text "1" at 9821.59,7514.94 h60
  text "Top Layer" at 10231.51,7514.94 h60
  text "1.38mil" at 12021.02,7514.94 h60
  text "Dielectric 1" at 10231.51,7394.94 h60
  text "FR-4 High Tg" at 11161.25,7394.94 h60
  text "3.94mil" at 12021.02,7394.94 h60
  text "4.3" at 12670.85,7394.94 h60
  text "2" at 9821.59,7274.94 h60
  text "GND" at 10231.51,7274.94 h60
  text "1.38mil" at 12021.02,7274.94 h60
  text "Dielectric 2" at 10231.51,7154.94 h60
  text "FR-4 High Tg" at 11161.25,7154.94 h60
  text "47.24mil" at 12021.02,7154.94 h60
  text "4.3" at 12670.85,7154.94 h60
  text "3" at 9821.59,7034.94 h60
  text "Power" at 10231.51,7034.94 h60
  text "1.38mil" at 12021.02,7034.94 h60
  text "Dielectric 3" at 10231.51,6914.94 h60
  text "FR-4 High Tg" at 11161.25,6914.94 h60
  text "3.94mil" at 12021.02,6914.94 h60
  text "4.3" at 12670.85,6914.94 h60
  text "4" at 9821.59,6794.94 h60
  text "Bottom Layer" at 10231.51,6794.94 h60
  text "1.38mil" at 12021.02,6794.94 h60
  text "Bottom Solder" at 10231.51,6674.94 h60
  text "Solder Resist" at 11161.25,6674.94 h60
  text "0.39mil" at 12021.02,6674.94 h60
  text "3.3" at 12670.85,6674.94 h60
  text "Bottom Overlay" at 10231.51,6554.94 h60
  text ".Layer_Name" at 577,-858.49 h60
M13 Component Bodies Top:
  text ".Layer_Name" at 577,-858.49 h60
M14 Component Bodies Bottom:
  text ".Layer_Name" at 577,-858.49 h60
M15 Courtyards Top:
  text ".Layer_Name" at 577,-858.49 h60
M16 Courtyards Bottom:
  text ".Layer_Name" at 577,-858.49 h60
Drill Drawing:
  lines w10: 5335.98,3263.15 5391.1,3263.15 5391.1,3318.28 5335.98,3318.28 5335.98,3263.15
  lines w12: 5286,3225.95 8512.8,3225.95 ; 5286,3349.97 8512.8,3349.97 ; 5623.36,3101.92 5623.36,3474 ; 5955.06,3101.92 5955.06,3474 ; 6590.91,3101.92 6590.91,3474 ; 6849.71,3101.92 6849.71,3474 ; 7224.46,3101.92 7224.46,3474 ; 7947,3101.92 7947,3474 ; 5286,3101.92 8512.8,3101.92 8512.8,3474 5286,3474 5286,3101.92
  text "Symbol" at 5360.42,3387.18 h72
  text "Quantity" at 5660.57,3387.18 h72
  text "Finished Hole Size" at 5992.26,3387.18 h72
  text "Plated" at 6628.12,3387.18 h72
  text "Hole Type" at 6886.92,3387.18 h72
  text "Drill Layer Pair" at 7261.67,3387.18 h72
  text "Hole Tolerance" at 7984.21,3387.18 h72
  text "168" at 5660.57,3263.15 h60
  text "8.00mil (0.203mm)" at 5992.26,3263.15 h60
  text "PTH" at 6628.12,3263.15 h60
  text "Round" at 6886.92,3263.15 h60
  text "Top Layer - Bottom Layer" at 7261.67,3263.15 h60
  text "168 Total" at 5660.57,3139.13 h60
  text ".Layer_Name" at 577,-858.49 h60
M17 Embedded Cavity:
  text ".Layer_Name" at 577,-858.49 h60
M18 Embedded Assembly:
  text ".Layer_Name" at 577,-858.49 h60
M19 Embedded Keepout:
  text ".Layer_Name" at 577,-858.49 h60

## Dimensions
600,550 to 600,1700 on M2 Board Dimensions
600,550 to 1425,550 on M2 Board Dimensions
0,-400 to 1000,-400 on M2 Board Dimensions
